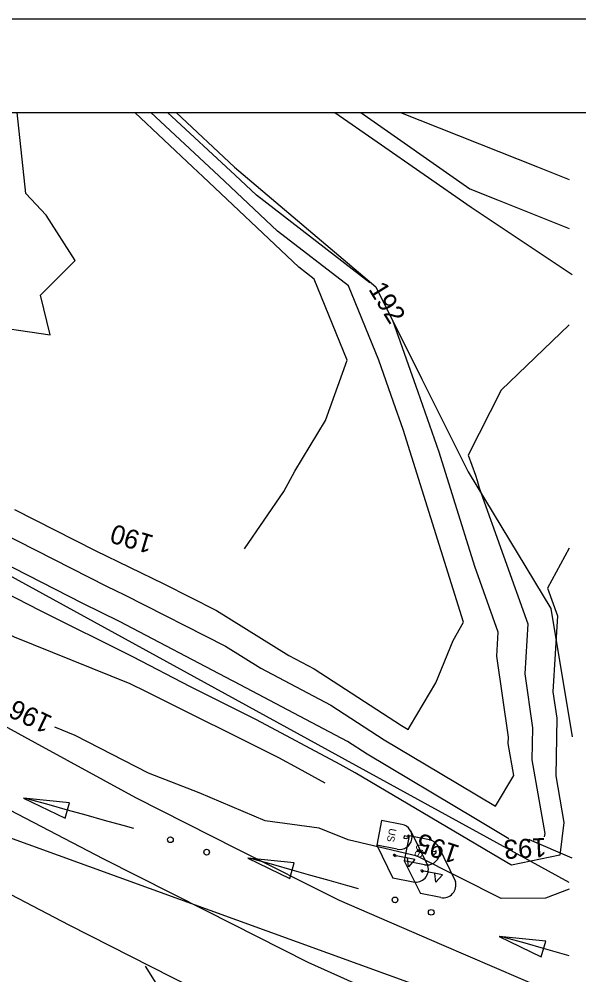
# Model space of a CAD drawing. Extents: x 1385284 to 1385995, y 1975154 to 1975620.
# Drawn here: x 1385675.6 to 1385748.9, y 1975494.4 to 1975619.6 of the extents above; entities that cross this region are included whole.
import ezdxf

# ---------------------------------------------------------------- set-up
doc = ezdxf.new("R2010")
doc.units = 0
for name, color, linetype in [('1', 7, 'Continuous'), ('Default', 7, 'Continuous'), ('DTM CONTOURS_MAJOR', 7, 'Continuous'), ('DTM_CONTOURS_MINOR', 7, 'Continuous'), ('R_Proposed Const Limits', 7, 'Continuous'), ('R_Special Ditch', 7, 'Continuous'), ('S_BASELINE', 7, 'Continuous'), ('S_CROSS_DRAIN', 7, 'Continuous'), ('S_DRG_PT_SYM', 7, 'Continuous'), ('S_DRIVEWAY', 7, 'Continuous'), ('S_EDGE_PAVEMENT', 7, 'Continuous'), ('S_LEVEE', 7, 'Continuous'), ('S_MAILBOX', 7, 'Continuous'), ('S_PAVEMENT_CROWN', 7, 'Continuous')]:
    doc.layers.add(name, color=color, linetype=linetype)

msp = doc.modelspace()

# ---------------------------------------------------------------- linework, layer by layer
at = {"layer": '1'}
msp.add_line((1385315.54, 1975607.41), (1385982.69, 1975607.41), dxfattribs=at)
for points in [[(1385994.75, 1975619.62), (1385283.84, 1975619.62), (1385283.84, 1975153.74), (1385994.75, 1975153.74)], [(1385315.54, 1975165.95), (1385315.54, 1975607.41), (1385810.69, 1975607.41), (1385810.69, 1975586.48), (1385892.57, 1975586.48), (1385892.57, 1975580.3), (1385982.69, 1975580.3), (1385982.69, 1975165.95)]]:
    msp.add_lwpolyline(points, close=True, dxfattribs=at)
at = {"layer": 'DTM CONTOURS_MAJOR'}
for points in [[(1385705.12, 1975550.22), (1385710.28, 1975557.74), (1385711.68, 1975560.4), (1385715.72, 1975567.04), (1385718.57, 1975574.95), (1385714.24, 1975585.58), (1385712.23, 1975587.14), (1385699.63, 1975599.02), (1385698.35, 1975600.21), (1385690.73, 1975607.41)], [(1385715.67, 1975519.53), (1385712.19, 1975521.46), (1385709.59, 1975522.85), (1385692.53, 1975531.37), (1385692.28, 1975531.5), (1385690.14, 1975532.56), (1385674.99, 1975538.68), (1385672.97, 1975539.73), (1385667.43, 1975543.91), (1385661.72, 1975546.84), (1385652.09, 1975551.76), (1385648.11, 1975553.8), (1385630.68, 1975563.01), (1385629.73, 1975563.43), (1385627.33, 1975565.48), (1385627.17, 1975565.49)]]:
    msp.add_lwpolyline(points, dxfattribs=at)
at = {"layer": 'DTM_CONTOURS_MINOR'}
for points in [[(1385651.09, 1975582.75), (1385652.05, 1975582.64), (1385659.93, 1975579.2), (1385670.13, 1975579.66), (1385679.68, 1975578.27), (1385678.41, 1975583.48), (1385682.93, 1975588), (1385679.15, 1975593.93), (1385676.46, 1975596.79), (1385675.32, 1975607.41)], [(1385674.99, 1975555.41), (1385685.53, 1975550.04), (1385694.56, 1975545.67), (1385701.45, 1975542.17), (1385710.9, 1975536.28), (1385714.25, 1975534.52), (1385725.66, 1975527.11), (1385726.1, 1975526.85), (1385726.55, 1975526.58), (1385726.84, 1975527.08), (1385730.17, 1975532.67), (1385732.45, 1975538.23), (1385733.78, 1975540.62), (1385729.51, 1975554.29), (1385725.89, 1975565.87), (1385724.63, 1975569.45), (1385722.7, 1975574.93), (1385718.72, 1975584.67), (1385709.45, 1975591.84), (1385701.76, 1975599.1), (1385692.83, 1975607.41)], [(1385721.51, 1975585.07), (1385706.67, 1975596.54), (1385703.88, 1975599.18), (1385695.03, 1975607.41)], [(1385720.35, 1975607.41), (1385734.62, 1975597.38), (1385738.24, 1975595.94), (1385747.64, 1975592.19)], [(1385725.53, 1975607.41), (1385743.47, 1975600.28), (1385747.64, 1975598.62)], [(1385668.38, 1975554.84), (1385687.04, 1975545.33), (1385689.38, 1975544.2), (1385702.6, 1975537.49), (1385707.25, 1975534.59), (1385716.42, 1975529.77), (1385723.42, 1975525.23), (1385730.73, 1975520.85), (1385737.99, 1975516.54), (1385740.36, 1975520.53), (1385739.64, 1975524.72), (1385739.66, 1975525.55), (1385738.16, 1975536.18), (1385738.34, 1975539.34), (1385735.28, 1975547.93), (1385732.53, 1975556.75), (1385730.62, 1975562.88), (1385727.83, 1975570.77), (1385724.53, 1975580.14)], [(1385747.64, 1975579.59), (1385738.7, 1975571.03), (1385734.42, 1975562.5), (1385735.34, 1975559.89), (1385735.56, 1975559.2), (1385735.86, 1975558.22), (1385742.21, 1975540.41), (1385741.83, 1975533.85), (1385742.82, 1975526.81), (1385742.75, 1975522.6), (1385744.42, 1975512.94), (1385744.36, 1975512.5)], [(1385747.64, 1975550.34), (1385744.79, 1975545.09), (1385746.08, 1975541.48), (1385745.5, 1975531.52), (1385745.99, 1975528.08), (1385745.86, 1975520.49), (1385746.91, 1975514.39), (1385746.4, 1975510.13), (1385740.08, 1975508.82), (1385740, 1975508.86), (1385739.48, 1975509.17), (1385719.59, 1975520.91), (1385717.62, 1975522.01), (1385706.69, 1975527.83), (1385698.03, 1975532.15), (1385690.5, 1975536.1), (1385678.38, 1975542.11), (1385672.17, 1975545.29), (1385663.68, 1975549.63), (1385657.45, 1975552.82), (1385647.74, 1975557.78), (1385636.08, 1975563.94), (1385631.2, 1975566.08), (1385630.38, 1975566.78)], [(1385739.74, 1975512.26), (1385735.37, 1975514.86), (1385721.17, 1975523.34), (1385718.59, 1975525.02), (1385704.55, 1975532.41), (1385703.8, 1975532.8), (1385703.54, 1975532.94), (1385688.72, 1975540.7), (1385683.95, 1975543.07), (1385669.5, 1975550.45)], [(1385747.64, 1975505.65), (1385744.53, 1975504.47), (1385738.71, 1975504.44), (1385727.7, 1975509.97), (1385718.68, 1975512.13), (1385714.87, 1975513.64), (1385707.83, 1975514.63), (1385699.15, 1975518.3), (1385692.55, 1975520.85), (1385682.94, 1975525.78), (1385680.27, 1975526.86)]]:
    msp.add_lwpolyline(points, dxfattribs=at)
at = {"layer": 'R_Proposed Const Limits'}
msp.add_lwpolyline([(1385747.64, 1975506.53), (1385668.29, 1975550.03)], dxfattribs=at)
at = {"layer": 'R_Special Ditch'}
for p, q in [((1385676.15, 1975517.59), (1385681.64, 1975514.95)), ((1385682.21, 1975516.99), (1385676.15, 1975517.59)), ((1385681.64, 1975514.95), (1385682.21, 1975516.99)), ((1385705.56, 1975509.71), (1385711.05, 1975507.07)), ((1385711.63, 1975509.11), (1385705.56, 1975509.71)), ((1385711.05, 1975507.07), (1385711.63, 1975509.11)), ((1385738.48, 1975499.45), (1385743.97, 1975496.81)), ((1385744.55, 1975498.85), (1385738.48, 1975499.45)), ((1385743.97, 1975496.81), (1385744.55, 1975498.85))]:
    msp.add_line(p, q, dxfattribs=at)
for points in [[(1385690.61, 1975513.59), (1385689.21, 1975513.99), (1385686.79, 1975514.67), (1385684.37, 1975515.35), (1385681.95, 1975516.02), (1385679.53, 1975516.7), (1385676.97, 1975517.42), (1385676.15, 1975517.59)], [(1385720.02, 1975505.72), (1385718.62, 1975506.11), (1385716.2, 1975506.79), (1385713.78, 1975507.47), (1385711.36, 1975508.15), (1385708.95, 1975508.83), (1385706.38, 1975509.55), (1385705.57, 1975509.71)], [(1385747.64, 1975496.94), (1385744.28, 1975497.89), (1385741.87, 1975498.57), (1385739.3, 1975499.29), (1385738.49, 1975499.45)]]:
    msp.add_lwpolyline(points, dxfattribs=at)
for centre in [(1385695.41, 1975512.13), (1385700.15, 1975510.51), (1385724.82, 1975504.26), (1385729.56, 1975502.63)]:
    msp.add_circle(centre, 0.375, dxfattribs=at)
at = {"layer": 'S_BASELINE'}
msp.add_line((1385611.25, 1975535.29), (1385748.02, 1975485.72), dxfattribs=at)
at = {"layer": 'S_CROSS_DRAIN'}
msp.add_line((1385748.02, 1975509.73), (1385742.41, 1975512.12), dxfattribs=at)
at = {"layer": 'S_DRG_PT_SYM'}
msp.add_lwpolyline([(1385742.41, 1975512.12), (1385742.46, 1975512.11), (1385742.41, 1975512.12), (1385742.42, 1975512.17), (1385742.41, 1975512.12), (1385742.36, 1975512.13), (1385742.41, 1975512.12), (1385742.4, 1975512.07)], dxfattribs=at)
at = {"layer": 'S_DRIVEWAY'}
msp.add_lwpolyline([(1385678.08, 1975404.98), (1385683.65, 1975419.06), (1385689.23, 1975433.14), (1385694.22, 1975445.55), (1385699.21, 1975457.96), (1385701.21, 1975471.01), (1385698.41, 1975485.54), (1385692.15, 1975495.56)], dxfattribs=at)
at = {"layer": 'S_EDGE_PAVEMENT'}
for points in [[(1385611.21, 1975560.34), (1385611.4, 1975560.24), (1385624.47, 1975553.3), (1385624.94, 1975553.05), (1385638.17, 1975545.98), (1385651.4, 1975538.99), (1385664.66, 1975531.98), (1385677.67, 1975524.86), (1385690.83, 1975517.66), (1385704.11, 1975510.96), (1385717.5, 1975504.2), (1385730.91, 1975498.41), (1385744.68, 1975492.46), (1385748.02, 1975491.02)], [(1385602.94, 1975543.48), (1385603.14, 1975543.37), (1385615.83, 1975536.54), (1385628.89, 1975529.16), (1385642.19, 1975522.14), (1385655.49, 1975515.19), (1385668.81, 1975507.91), (1385682.12, 1975501), (1385695.61, 1975494.13), (1385709, 1975487.36), (1385723.17, 1975481.26), (1385736.98, 1975475.38), (1385748.02, 1975470.82)]]:
    msp.add_lwpolyline(points, dxfattribs=at)
at = {"layer": 'S_LEVEE'}
for points in [[(1385696.16, 1975607.41), (1385703.8, 1975600.23), (1385722.29, 1975584.55), (1385728.34, 1975572.44), (1385734.4, 1975560.32), (1385745.22, 1975542.44), (1385748.02, 1975525.6)], [(1385716.95, 1975607.41), (1385722.48, 1975603.55), (1385734.78, 1975594.97), (1385748.02, 1975586.15)]]:
    msp.add_lwpolyline(points, dxfattribs=at)
at = {"layer": 'S_MAILBOX'}
for p, q in [((1385723.06, 1975514.67), (1385722.42, 1975511.41)), ((1385725.72, 1975514.15), (1385723.06, 1975514.67)), ((1385726.86, 1975513.36), (1385729.12, 1975508.7)), ((1385726.67, 1975512.64), (1385726.03, 1975509.38)), ((1385729.33, 1975512.12), (1385726.67, 1975512.64)), ((1385725.08, 1975510.88), (1385722.42, 1975511.41)), ((1385722.42, 1975511.41), (1385724.54, 1975507.12)), ((1385730.47, 1975511.33), (1385732.73, 1975506.67)), ((1385727.43, 1975509.56), (1385724.77, 1975510.08)), ((1385728.69, 1975508.85), (1385726.03, 1975509.38)), ((1385726.03, 1975509.38), (1385728.15, 1975505.09)), ((1385731.04, 1975507.53), (1385728.38, 1975508.05)), ((1385727.21, 1975506.6), (1385724.54, 1975507.12)), ((1385730.82, 1975504.57), (1385728.15, 1975505.09))]:
    msp.add_line(p, q, dxfattribs=at)
for points in [[(1385726.59, 1975512.77), (1385726.41, 1975512.58), (1385726.03, 1975512.65), (1385725.97, 1975512.35), (1385726.32, 1975512.29), (1385726.6, 1975512.43), (1385726.61, 1975512.77)], [(1385730.2, 1975510.74), (1385730.02, 1975510.55), (1385729.64, 1975510.62), (1385729.58, 1975510.33), (1385729.93, 1975510.26), (1385730.21, 1975510.4), (1385730.22, 1975510.74)], [(1385727.43, 1975509.56), (1385726.57, 1975508.6), (1385726.44, 1975509.76)], [(1385731.04, 1975507.53), (1385730.18, 1975506.57), (1385730.05, 1975507.73)]]:
    msp.add_lwpolyline(points, dxfattribs=at)
for centre, end in [((1385725.4, 1975512.52), 78.9164), ((1385729.01, 1975510.49), 78.9164), ((1385727.53, 1975508.23), 16.4883), ((1385731.14, 1975506.2), 16.4883)]:
    msp.add_arc(centre, 1.66, 258.9164, end, dxfattribs=at)
for centre in [(1385724.77, 1975510.08), (1385728.38, 1975508.05)]:
    msp.add_ellipse(centre, major_axis=(0.101, -0.168), ratio=0.564646, dxfattribs=at)
at = {"layer": 'S_PAVEMENT_CROWN'}
msp.add_lwpolyline([(1385607.45, 1975552.41), (1385607.52, 1975552.37), (1385607.52, 1975552.37), (1385620.51, 1975545.21), (1385620.58, 1975545.17), (1385633.72, 1975537.92), (1385646.88, 1975530.73), (1385660.05, 1975523.54), (1385673.34, 1975516.59), (1385686.64, 1975509.64), (1385700.03, 1975502.88), (1385713.42, 1975496.12), (1385727.09, 1975489.95), (1385740.77, 1975483.78), (1385748.02, 1975480.77)], dxfattribs=at)

# ---------------------------------------------------------------- texts
at = {"layer": 'Default'}
for s, rotation, p in [('192', 301.5049, (1385721.28, 1975584.25)), ('190', 163.4273, (1385693.37, 1975551.93)), ('196', 154.6316, (1385680.11, 1975528.2)), ('195', 161.5368, (1385733.44, 1975511.29)), ('193', 182.9624, (1385744.58, 1975512.39))]:
    msp.add_text(s, height=2.5, rotation=rotation, dxfattribs=at).set_placement(p)
at = {"layer": 'S_MAILBOX'}
for p in [(1385724.08, 1975513.69), (1385727.69, 1975511.66)]:
    msp.add_text('US', height=0.96, rotation=258.9164, dxfattribs=at).set_placement(p)

doc.saveas('drawing.dxf')
